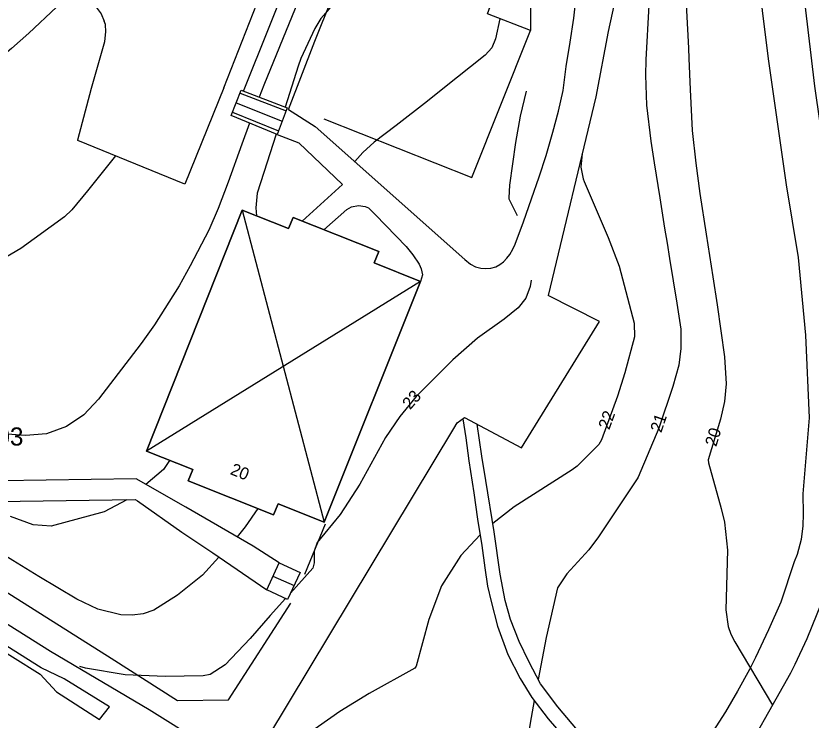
# Model space of a CAD drawing. Extents: x 67169 to 69652, y 20189 to 22818.
# Drawn here: x 69362.6 to 69428.4, y 21206.6 to 21264.9 of the extents above; entities that cross this region are included whole.
import ezdxf

# ---------------------------------------------------------------- set-up
doc = ezdxf.new("R2010")
doc.units = 0
for name, color, linetype in [('BYGGNAD_HUSLIV', 7, 'Continuous'), ('BYGGNAD_HUSLIV 11', 7, 'Continuous'), ('BYGGNADSDETALJER', 7, 'Continuous'), ('BYGGNADSDETALJER 19', 7, 'Continuous'), ('BYGGNADSSYMBOLER', 7, 'Continuous'), ('BYGGNADSSYMBOLER 30', 7, 'Continuous'), ('HOJDKURVOR_2014', 7, 'Continuous'), ('HOJDKURVOR_2014 5M', 7, 'Continuous'), ('HOJDKURVOR_TEXTER_2014', 7, 'Continuous'), ('Instruktioner', 7, 'Continuous'), ('MUR_STAKET', 7, 'Continuous'), ('MUR_STAKET_SYMBOL', 7, 'Continuous'), ('Std_Ritningsstämpel', 7, 'Continuous'), ('STOMPUNKTER TEXT', 7, 'Continuous'), ('VAGAR 121', 7, 'Continuous'), ('VAGAR 123', 7, 'Continuous')]:
    doc.layers.add(name, color=color, linetype=linetype)

msp = doc.modelspace()

# ---------------------------------------------------------------- linework, layer by layer
at = {"layer": 'BYGGNAD_HUSLIV'}
msp.add_lwpolyline([(69381.34, 21248.815), (69385.174, 21247.283), (69385.544, 21248.21), (69392.629, 21245.38), (69392.259, 21244.452), (69396.086, 21242.921), (69388.113, 21223.015), (69384.313, 21224.533), (69383.942, 21223.604), (69376.885, 21226.423), (69377.256, 21227.354), (69373.421, 21228.886), (69381.34, 21248.815)], dxfattribs=at)
at = {"layer": 'BYGGNAD_HUSLIV 11'}
msp.add_lwpolyline([(69381.34, 21248.815), (69385.174, 21247.283), (69385.544, 21248.21), (69392.629, 21245.38), (69392.259, 21244.452), (69396.086, 21242.921), (69388.113, 21223.015), (69384.313, 21224.533), (69383.942, 21223.604), (69376.885, 21226.423), (69377.256, 21227.354), (69373.421, 21228.886), (69381.34, 21248.815)], dxfattribs=at)
at = {"layer": 'BYGGNADSDETALJER'}
for p, q in [((69381.162, 21258.486), (69384.973, 21257.023)), ((69380.54, 21256.912), (69384.339, 21255.358))]:
    msp.add_line(p, q, dxfattribs=at)
for points in [[(69384.231, 21255.074), (69380.425, 21256.622), (69381.256, 21258.723), (69385.062, 21257.259), (69384.231, 21255.074)], [(69384.399, 21219.656), (69386.125, 21218.854), (69385.096, 21216.608), (69383.37, 21217.409), (69384.399, 21219.656)]]:
    msp.add_lwpolyline(points, dxfattribs=at)
at = {"layer": 'BYGGNADSDETALJER 19'}
for p, q in [((69381.162, 21258.486), (69384.973, 21257.023)), ((69380.54, 21256.912), (69384.339, 21255.358))]:
    msp.add_line(p, q, dxfattribs=at)
for points in [[(69384.231, 21255.074), (69380.425, 21256.622), (69381.256, 21258.723), (69385.062, 21257.259), (69384.231, 21255.074)], [(69384.399, 21219.656), (69386.125, 21218.854), (69385.096, 21216.608), (69383.37, 21217.409), (69384.399, 21219.656)]]:
    msp.add_lwpolyline(points, dxfattribs=at)
at = {"layer": 'BYGGNADSSYMBOLER'}
for p, q in [((69380.841, 21257.672), (69384.647, 21256.166)), ((69380.841, 21257.672), (69380.841, 21257.672)), ((69381.34, 21248.815), (69388.113, 21223.015)), ((69396.086, 21242.921), (69373.421, 21228.886)), ((69383.882, 21218.541), (69385.626, 21217.766)), ((69383.882, 21218.541), (69383.882, 21218.541))]:
    msp.add_line(p, q, dxfattribs=at)
at = {"layer": 'BYGGNADSSYMBOLER 30'}
for p, q in [((69381.34, 21248.815), (69388.113, 21223.015)), ((69396.086, 21242.921), (69373.421, 21228.886))]:
    msp.add_line(p, q, dxfattribs=at)
at = {"layer": 'HOJDKURVOR_2014'}
for points in [[(69390.056, 21274.09), (69389.939, 21273.486), (69389.547, 21272.582), (69387.675, 21268.953), (69385.976, 21266.085), (69385.71, 21265.48), (69383.133, 21259.153), (69382.74, 21258.152)], [(69367.175, 21266.967), (69366.936, 21266.605), (69366.257, 21265.822), (69366.009, 21265.58), (69363.704, 21263.443), (69362.278, 21262.161), (69359.337, 21259.705), (69357.821, 21258.53), (69354.449, 21255.997), (69353.343, 21255.257), (69350.982, 21254.075), (69348.891, 21253.425)], [(69414.956, 21265.759), (69414.698, 21261.223), (69414.662, 21259.979), (69414.75, 21257.497), (69415.1, 21254.509), (69415.4, 21252.71), (69415.858, 21249.839), (69416.252, 21247.327), (69416.455, 21246.072), (69416.661, 21244.817), (69417.274, 21241.111), (69417.581, 21238.977), (69417.598, 21237.383), (69417.417, 21235.986), (69416.924, 21234.221), (69415.764, 21230.793), (69414.06, 21226.727), (69413.975, 21226.593), (69410.796, 21221.807), (69409.998, 21220.72), (69408.179, 21218.727), (69407.408, 21217.589), (69406.46, 21213.489), (69405.801, 21209.991)], [(69402.641, 21264.634), (69402.284, 21262.986), (69401.968, 21262.226), (69401.419, 21261.612), (69397.927, 21258.831), (69396.649, 21257.819), (69394.077, 21255.813), (69392.259, 21254.42), (69391.313, 21253.564), (69390.65, 21252.819)], [(69404.804, 21258.656), (69404.322, 21256.577), (69403.922, 21254.414), (69403.43, 21250.867), (69403.369, 21249.824), (69403.39, 21249.755), (69404.059, 21248.367)], [(69381.939, 21256.006), (69381.307, 21254.252), (69380.17, 21251.116), (69379.362, 21248.943), (69378.59, 21247.159), (69377.054, 21244.205), (69376.133, 21242.538), (69374.098, 21239.327), (69372.984, 21237.782), (69369.478, 21233.174), (69368.268, 21231.898), (69366.813, 21230.911), (69365.179, 21230.311), (69363.445, 21230.169), (69361.914, 21230.297), (69359.754, 21230.717), (69358.695, 21231.032), (69354.221, 21232.57), (69351.719, 21233.421), (69351.205, 21233.592)], [(69370.866, 21253.296), (69368.553, 21250.407), (69367.254, 21248.823), (69366.662, 21248.264), (69363.037, 21245.629), (69361.453, 21244.701), (69359.799, 21243.985), (69358.041, 21243.59), (69356.214, 21243.409), (69353.796, 21243.419), (69351.105, 21243.547), (69349.278, 21243.709), (69347.64, 21243.802)], [(69409.442, 21253.471), (69409.336, 21252.364), (69409.529, 21251.408), (69409.616, 21251.179), (69411.591, 21246.554), (69412.493, 21244.169), (69413.726, 21239.451), (69413.765, 21238.324), (69412.974, 21235.371), (69412.349, 21233.429), (69411.022, 21229.807), (69410.826, 21229.437), (69409.031, 21227.649), (69408.599, 21227.345), (69403.831, 21224.273), (69402.051, 21222.907)], [(69405.233, 21243.022), (69405.152, 21242.508), (69404.788, 21241.545), (69404.158, 21240.731), (69403.003, 21239.793), (69400.796, 21238.219), (69398.753, 21236.437), (69395.732, 21233.388), (69394.382, 21231.759), (69393.197, 21230.007), (69391.071, 21226.162), (69389.443, 21223.645), (69387.528, 21221.333), (69387.278, 21220.604), (69387.3, 21219.64), (69387.18, 21219.21), (69385.346, 21217.154)], [(69379.425, 21220.122), (69378.064, 21218.637), (69375.99, 21216.976), (69374.032, 21215.741), (69373.166, 21215.428), (69372.252, 21215.319), (69371.306, 21215.345), (69369.424, 21215.809), (69367.685, 21216.631), (69364.541, 21218.524), (69362.389, 21219.839), (69359.618, 21221.55), (69355.394, 21223.589), (69355.203, 21223.677), (69346.67, 21228.12), (69346.034, 21228.453), (69344.764, 21229.124), (69342.6, 21230.293), (69339.087, 21231.963), (69334.403, 21233.357), (69332.158, 21233.767)], [(69382.622, 21224.131), (69381.597, 21222.623), (69380.923, 21221.786)], [(69401.004, 21221.966), (69399.416, 21220.265), (69397.818, 21217.756), (69396.759, 21214.975), (69395.715, 21211.11), (69395.602, 21210.93), (69391.846, 21208.859), (69389.418, 21207.353), (69386.622, 21205.406), (69384.593, 21203.795), (69383.131, 21202.674), (69382.213, 21202.14)], [(69384.925, 21216.687), (69383.653, 21215.281), (69381.992, 21213.4), (69379.928, 21211.226), (69378.706, 21210.416), (69378.116, 21210.312), (69374.983, 21210.245), (69371.672, 21210.386), (69368.406, 21210.947), (69367.918, 21211.077)], [(69405.482, 21208.267), (69405.15, 21206.386), (69404.941, 21205.2), (69403.676, 21198.005), (69403.664, 21197.952), (69403.649, 21197.9), (69403.628, 21197.85), (69400.658, 21194.747), (69400.296, 21194.211)]]:
    msp.add_lwpolyline(points, dxfattribs=at)
at = {"layer": 'HOJDKURVOR_2014 5M'}
for points in [[(69393.453, 21272.723), (69393.37, 21272.422), (69392.354, 21270.069), (69392.144, 21269.798), (69388.053, 21264.912), (69387.853, 21264.656), (69387.335, 21263.83), (69386.198, 21261.349), (69385.974, 21260.71), (69384.88, 21257.329)], [(69417.748, 21271.035), (69418.223, 21262.202), (69418.265, 21261.35), (69418.353, 21258.793), (69418.514, 21255.391), (69418.834, 21252.694), (69419.171, 21250.174), (69419.676, 21246.816), (69420.237, 21243.303), (69420.6, 21240.986), (69421.205, 21236.692), (69421.328, 21234.456), (69421.213, 21232.978), (69420.874, 21231.534), (69419.844, 21228.162), (69419.868, 21227.927), (69420.935, 21224.15), (69421.196, 21223.011), (69421.456, 21220.704), (69421.322, 21215.761), (69421.5, 21214.388), (69421.734, 21213.741), (69422.041, 21213.114), (69425.169, 21207.885)], [(69384.16, 21255.103), (69383.127, 21251.911), (69382.844, 21251.065), (69382.572, 21250.217), (69382.457, 21249.008), (69382.513, 21248.346)], [(69375.343, 21228.118), (69374.826, 21227.373), (69373.38, 21226.133)], [(69371.808, 21224.863), (69369.948, 21223.867), (69365.544, 21222.692), (69364.08, 21222.786), (69362.186, 21223.476)]]:
    msp.add_lwpolyline(points, dxfattribs=at)
at = {"layer": 'MUR_STAKET'}
msp.add_line((69386.515, 21218.714), (69388.228, 21222.886), dxfattribs=at)
for points in [[(69402.109, 21277.244), (69404.787, 21276.153), (69405.146, 21274.761), (69405.166, 21263.65)], [(69381.462, 21258.643), (69383.613, 21264.086), (69385.027, 21267.616), (69385.796, 21269.516), (69388.35, 21275.909)], [(69385.157, 21257.133), (69387.341, 21262.785), (69391.623, 21273.459)], [(69403.887, 21245.991), (69404.586, 21247.842), (69405.259, 21249.743), (69405.89, 21251.557), (69406.456, 21253.326), (69407.013, 21255.267), (69407.487, 21257.004), (69407.866, 21258.692), (69408.117, 21260.676), (69408.453, 21262.702), (69408.747, 21264.686), (69408.98, 21266.712)], [(69388.091, 21256.355), (69400.324, 21251.511), (69405.166, 21263.65)], [(69296.097, 21258.84), (69302.521, 21254.777), (69308.499, 21251), (69318.674, 21244.588), (69325.225, 21240.445), (69336.99, 21232.986), (69342.364, 21229.574), (69352.603, 21223.178), (69355.624, 21221.194), (69360.68, 21217.972), (69370.521, 21211.767), (69376.007, 21208.274), (69380.202, 21208.309), (69385.375, 21216.324)]]:
    msp.add_lwpolyline(points, dxfattribs=at)
at = {"layer": 'MUR_STAKET_SYMBOL'}
for p, q in [((69383.53, 21263.879), (69383.53, 21263.879)), ((69387.712, 21263.708), (69387.712, 21263.708)), ((69408.671, 21264.2), (69408.671, 21264.2)), ((69382.991, 21262.516), (69382.991, 21262.516)), ((69408.452, 21262.722), (69408.452, 21262.722)), ((69387.165, 21262.336), (69387.165, 21262.336)), ((69382.45, 21261.144), (69382.45, 21261.144)), ((69408.204, 21261.201), (69408.204, 21261.201)), ((69386.623, 21260.933), (69386.623, 21260.933)), ((69407.996, 21259.735), (69407.996, 21259.735)), ((69381.88, 21259.702), (69381.88, 21259.702)), ((69386.082, 21259.53), (69386.082, 21259.53)), ((69381.461, 21258.643), (69381.461, 21258.643)), ((69407.82, 21258.487), (69407.82, 21258.487)), ((69385.581, 21258.233), (69385.581, 21258.233)), ((69402.489, 21256.936), (69402.489, 21256.936)), ((69407.493, 21257.034), (69407.493, 21257.034)), ((69407.138, 21255.725), (69407.138, 21255.725)), ((69393.705, 21254.13), (69393.705, 21254.13)), ((69406.738, 21254.315), (69406.738, 21254.315)), ((69406.31, 21252.876), (69406.31, 21252.876)), ((69405.903, 21251.604), (69405.903, 21251.604)), ((69405.428, 21250.229), (69405.428, 21250.229)), ((69404.936, 21248.834), (69404.936, 21248.834)), ((69404.42, 21247.402), (69404.42, 21247.402)), ((69403.887, 21245.991), (69403.887, 21245.991)), ((69388.047, 21222.446), (69388.047, 21222.446)), ((69387.29, 21220.604), (69387.29, 21220.604)), ((69386.537, 21218.768), (69386.537, 21218.768)), ((69362.775, 21216.65), (69362.775, 21216.65)), ((69364.571, 21215.518), (69364.571, 21215.518)), ((69384.875, 21215.549), (69384.875, 21215.549)), ((69366.212, 21214.483), (69366.212, 21214.483)), ((69383.842, 21213.949), (69383.842, 21213.949)), ((69367.935, 21213.397), (69367.935, 21213.397)), ((69369.625, 21212.331), (69369.625, 21212.331)), ((69382.716, 21212.205), (69382.716, 21212.205)), ((69371.238, 21211.309), (69371.238, 21211.309)), ((69381.607, 21210.488), (69381.607, 21210.488)), ((69372.967, 21210.209), (69372.967, 21210.209)), ((69374.683, 21209.116), (69374.683, 21209.116)), ((69380.527, 21208.812), (69380.527, 21208.812)), ((69376.493, 21208.277), (69376.493, 21208.277)), ((69378.377, 21208.294), (69378.377, 21208.294))]:
    msp.add_line(p, q, dxfattribs=at)
at = {"layer": 'Std_Ritningsstämpel'}
msp.add_lwpolyline([(69381.34, 21248.815), (69373.421, 21228.886), (69377.256, 21227.354), (69376.885, 21226.423), (69383.942, 21223.604), (69384.313, 21224.533), (69388.113, 21223.015), (69396.086, 21242.921), (69392.259, 21244.452), (69392.629, 21245.38), (69385.544, 21248.21), (69385.174, 21247.283)], close=True, dxfattribs=at)
at = {"layer": 'VAGAR 121'}
for points in [[(69379.822, 21258.929), (69383.159, 21267.446)], [(69379.822, 21258.929), (69376.599, 21250.961), (69367.754, 21254.564), (69367.768, 21254.622), (69368.89, 21258.905), (69369.996, 21262.766), (69370.085, 21263.559), (69370.039, 21264.171), (69369.949, 21264.44)], [(69385.157, 21257.133), (69387.384, 21255.732), (69399.739, 21244.715), (69400.219, 21244.331), (69400.63, 21244.11), (69401.064, 21244.004), (69401.475, 21243.974), (69401.886, 21244.005), (69402.296, 21244.132), (69402.623, 21244.302), (69402.929, 21244.534), (69403.224, 21244.84), (69403.466, 21245.135), (69403.718, 21245.579), (69403.887, 21245.991)], [(69384.231, 21255.074), (69386.014, 21254.369), (69389.634, 21250.923), (69386.301, 21247.907)], [(69388.09, 21247.192), (69389.986, 21248.858), (69390.38, 21249.092), (69390.95, 21249.194), (69391.491, 21249.108), (69391.783, 21248.991), (69392.369, 21248.421), (69394.9, 21245.792), (69395.442, 21245.12), (69395.979, 21244.35), (69396.128, 21243.96), (69396.233, 21243.474), (69396.086, 21242.921)], [(69414.588, 21194.783), (69411.905, 21193.251), (69407.788, 21192.494), (69397.41, 21194.848), (69395.417, 21195.526), (69393.831, 21196.082), (69391.918, 21196.785), (69390.97, 21197.161), (69390.071, 21197.553), (69387.928, 21198.566), (69386.032, 21199.748), (69373.666, 21207.495), (69365.496, 21212.309), (69349.694, 21222.267), (69330.773, 21234.25), (69319.82, 21241.201), (69318.929, 21241.754), (69315.325, 21244.041), (69313.082, 21245.432)], [(69369.563, 21206.707), (69370.364, 21207.754), (69366.633, 21210.061), (69364.732, 21210.966), (69348.944, 21220.921), (69329.559, 21233.233), (69318.958, 21239.889), (69317.843, 21240.643), (69316.752, 21241.388)], [(69369.563, 21206.707), (69370.364, 21207.754), (69366.633, 21210.061), (69364.732, 21210.966), (69348.944, 21220.921), (69329.559, 21233.233), (69318.958, 21239.889), (69317.843, 21240.643), (69316.752, 21241.388)], [(69383.474, 21205.2), (69398.827, 21230.748), (69399.112, 21231.224), (69399.716, 21231.67), (69404.422, 21229.163), (69410.865, 21239.593), (69406.636, 21241.752)], [(69431.132, 21222.657), (69430.785, 21221.585), (69430.659, 21220.809), (69430.279, 21219.299), (69429.852, 21217.996), (69429.661, 21217.456), (69427.997, 21213.37), (69427.012, 21211.24), (69426.664, 21210.54), (69422.063, 21202.369), (69418.539, 21198.138), (69417.094, 21196.787), (69416.093, 21195.975), (69414.588, 21194.783)], [(69348.607, 21220.462), (69364.637, 21210.441), (69365.993, 21208.976), (69369.563, 21206.707)]]:
    msp.add_lwpolyline(points, dxfattribs=at)
at = {"layer": 'VAGAR 123'}
for points in [[(69415.51, 21291.02), (69415.641, 21295.031), (69415.148, 21296.42), (69414.296, 21297.365), (69414.617, 21306.543), (69416.075, 21308.606), (69417.548, 21309.131), (69418.87, 21308.663), (69420.952, 21293.399), (69423.357, 21273.119), (69424.797, 21261.333), (69426.295, 21250.906), (69427.29, 21244.89), (69427.899, 21238.468), (69428.199, 21231.65), (69427.684, 21225.344)], [(69429.852, 21309.408), (69425.625, 21308.81), (69423.314, 21308.399), (69422.714, 21307.312), (69423.237, 21303.827), (69424.984, 21289.321), (69426.536, 21276.782), (69428.635, 21259.05), (69429.946, 21249.893), (69430.862, 21243.778), (69431.231, 21240.653), (69431.817, 21235.059), (69431.598, 21226.403)], [(69415.51, 21291.02), (69415.122, 21284.949), (69414.548, 21274.78), (69413.888, 21271.563), (69412.245, 21266.651), (69411.583, 21263.567), (69410.569, 21258.181), (69406.636, 21241.752)], [(69405.166, 21263.65), (69401.602, 21265.039), (69405.146, 21274.761)], [(69350.857, 21258.946), (69350.978, 21259.579), (69350.932, 21260.305), (69350.682, 21261.234), (69350.637, 21261.551), (69350.636, 21261.868), (69350.862, 21262.48), (69351.157, 21262.799), (69354.124, 21264.704), (69357.793, 21267.042), (69360.331, 21268.721), (69361.259, 21269.266), (69362.392, 21269.675), (69362.647, 21269.624), (69363.327, 21269.285), (69364.405, 21268.595), (69366.479, 21267.395), (69368.815, 21265.958), (69369.268, 21265.584), (69369.688, 21265.052), (69369.949, 21264.44)], [(69384.399, 21219.656), (69382.247, 21221.017), (69376.688, 21224.246), (69372.585, 21226.587), (69361.431, 21226.426), (69348.75, 21235.313), (69348.533, 21235.703), (69348.009, 21239.37), (69347.681, 21242.907), (69347.614, 21244.382), (69347.72, 21247.073), (69348.195, 21250.546), (69348.887, 21253.412), (69349.904, 21256.536), (69350.705, 21258.577), (69350.857, 21258.946)], [(69399.576, 21231.567), (69399.836, 21229.988), (69400.077, 21228.081), (69400.492, 21225.443), (69400.796, 21223.266), (69401.147, 21221.074), (69401.388, 21219.231), (69401.611, 21217.721), (69401.93, 21216.45), (69402.441, 21214.401), (69403.285, 21212.081), (69404.319, 21210.08), (69405.29, 21208.523), (69406.626, 21206.745), (69413.991, 21198.2)], [(69409.791, 21204.935), (69407.436, 21207.73), (69405.988, 21209.636), (69405.017, 21211.478), (69404.237, 21213.131), (69403.504, 21214.973), (69403.074, 21216.531), (69402.659, 21218.707), (69402.163, 21222.219), (69401.476, 21226.446), (69401.141, 21228.48), (69400.751, 21231.12)], [(69427.684, 21225.344), (69427.701, 21223.702), (69427.67, 21222.716), (69427.528, 21221.572), (69427.211, 21220.332), (69426.957, 21219.743), (69425.863, 21216.39), (69424.848, 21214.117), (69423.769, 21211.812), (69423.262, 21210.826), (69422.262, 21209.045), (69421.294, 21207.328), (69419.992, 21205.308)], [(69361.053, 21224.732), (69372.489, 21224.872), (69372.684, 21224.785), (69376.354, 21222.184), (69378.917, 21220.472), (69383.37, 21217.409)]]:
    msp.add_lwpolyline(points, dxfattribs=at)

# ---------------------------------------------------------------- texts
at = {"layer": 'HOJDKURVOR_TEXTER_2014'}
for s, rotation, p in [('23', 48.29533, (69395.216, 21232.26)), ('22', 69.87474, (69411.672, 21230.594)), ('21', 71.18721, (69415.973, 21230.359)), ('20', 73.00727, (69420.517, 21229.201))]:
    msp.add_text(s, height=1, rotation=rotation, dxfattribs=at).set_placement(p)
at = {"layer": 'Instruktioner'}
msp.add_text('20', height=1, rotation=338.16659, dxfattribs=at).set_placement((69380.284, 21226.996))
at = {"layer": 'STOMPUNKTER TEXT'}
msp.add_text('5103', height=1.5, dxfattribs=at).set_placement((69358.802, 21229.344))

doc.saveas('drawing.dxf')
